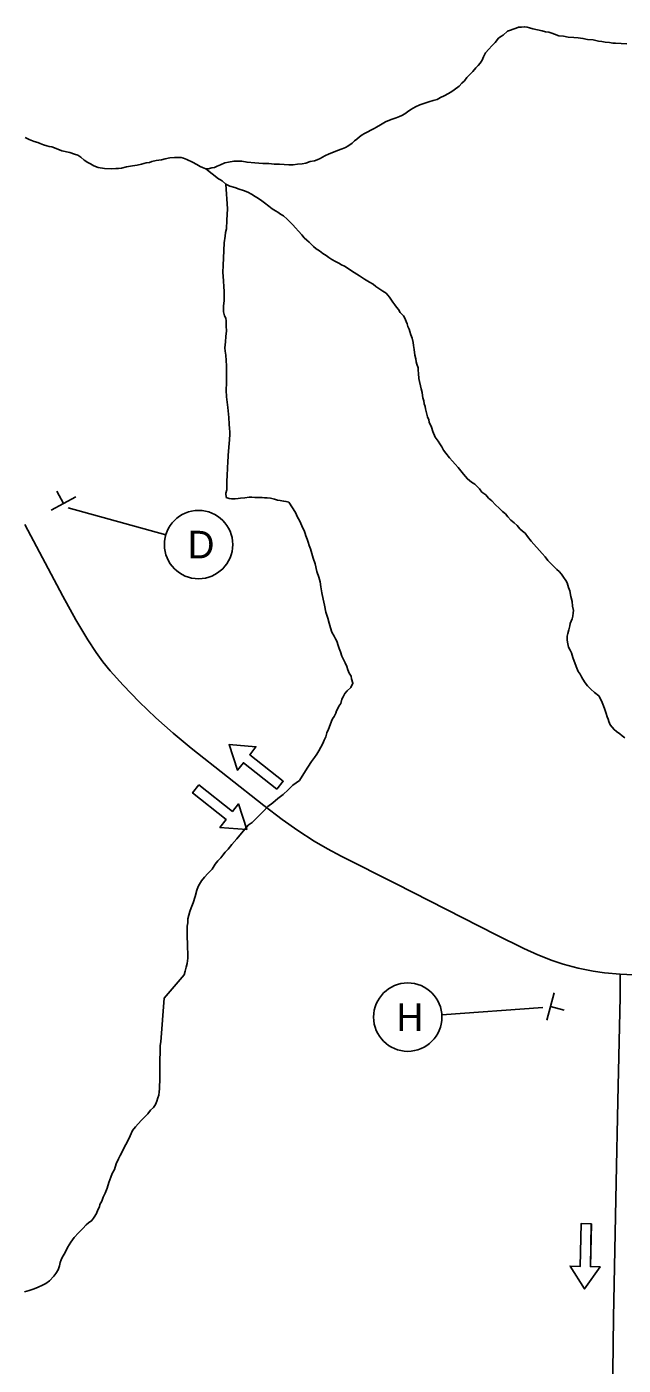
# Model space of a CAD drawing. Extents: x 1633.3 to 1707.6, y 1081.5 to 1106.
# Drawn here: x 1640.87 to 1644.25, y 1094.16 to 1101.73 of the extents above; entities that cross this region are included whole.
import ezdxf

# ---------------------------------------------------------------- set-up
doc = ezdxf.new("R2010")
doc.units = 0
for name, color, linetype in [('GM_X_County_Road', 7, 'Continuous'), ('GM_X_Minor_River', 7, 'Continuous'), ('GM_X_State_Route', 7, 'Continuous'), ('SH_Text', 7, 'Continuous'), ('SN_P_Signs', 7, 'Continuous')]:
    doc.layers.add(name, color=color, linetype=linetype)

msp = doc.modelspace()

# ---------------------------------------------------------------- linework, layer by layer
at = {"layer": 'GM_X_County_Road'}
msp.add_lwpolyline([(1644.102, 1092.8585), (1644.1321, 1092.8991), (1644.152, 1092.9386), (1644.1601, 1092.9592), (1644.1702, 1093.0024), (1644.1728, 1093.0244), (1644.1756, 1093.0686), (1644.1758, 1093.3536), (1644.1865, 1093.8566), (1644.1891, 1094.1191), (1644.194, 1094.4253), (1644.2086, 1095.1908), (1644.2171, 1095.6502), (1644.2319, 1096.2407), (1644.2313, 1096.3288), (1644.2311, 1096.3693)], dxfattribs=at)
at = {"layer": 'GM_X_Minor_River'}
for points in [[(1641.8974, 1100.9286), (1641.9189, 1100.9337), (1641.9324, 1100.9362), (1641.9486, 1100.944), (1641.9675, 1100.9518), (1641.9918, 1100.9622), (1642.0133, 1100.9673), (1642.043, 1100.9723), (1642.0698, 1100.9719), (1642.0886, 1100.9717), (1642.1181, 1100.9659), (1642.161, 1100.9627), (1642.2066, 1100.9594), (1642.2415, 1100.9589), (1642.271, 1100.9559), (1642.3006, 1100.9555), (1642.3274, 1100.9525), (1642.3542, 1100.9521), (1642.3784, 1100.9518), (1642.4026, 1100.9541), (1642.4295, 1100.9565), (1642.451, 1100.9615), (1642.4753, 1100.9693), (1642.4995, 1100.9743), (1642.5157, 1100.9794), (1642.5319, 1100.9873), (1642.559, 1101.003), (1642.5833, 1101.0134), (1642.6076, 1101.0238), (1642.6292, 1101.0315), (1642.6561, 1101.0419), (1642.675, 1101.0497), (1642.6886, 1101.0575), (1642.7129, 1101.0733), (1642.7265, 1101.0865), (1642.7401, 1101.097), (1642.7537, 1101.1103), (1642.7699, 1101.1208), (1642.7835, 1101.1286), (1642.8375, 1101.1574), (1642.851, 1101.1652), (1642.8727, 1101.1783), (1642.9024, 1101.194), (1642.9348, 1101.207), (1642.9618, 1101.2174), (1642.9807, 1101.2251), (1642.9942, 1101.2303), (1643.0105, 1101.2408), (1643.0267, 1101.2513), (1643.0457, 1101.2645), (1643.0727, 1101.2802), (1643.097, 1101.2906), (1643.124, 1101.3009), (1643.1483, 1101.3087), (1643.1725, 1101.3164), (1643.1941, 1101.3215), (1643.213, 1101.3319), (1643.2346, 1101.3424), (1643.259, 1101.3554), (1643.2779, 1101.3659), (1643.2915, 1101.3764), (1643.3186, 1101.3975), (1643.3349, 1101.4134), (1643.3485, 1101.4266), (1643.3621, 1101.4451), (1643.3812, 1101.4637), (1643.3975, 1101.4795), (1643.4139, 1101.5007), (1643.4275, 1101.5139), (1643.4384, 1101.5272), (1643.4493, 1101.5431), (1643.4576, 1101.5618), (1643.4687, 1101.5857), (1643.4877, 1101.6069), (1643.5041, 1101.6255), (1643.5231, 1101.6439), (1643.5422, 1101.6678), (1643.5558, 1101.6783), (1643.5693, 1101.6862), (1643.5937, 1101.7073), (1643.6423, 1101.7254), (1643.6558, 1101.7306), (1643.6719, 1101.7304), (1643.688, 1101.7329), (1643.7041, 1101.73), (1643.7175, 1101.7271), (1643.7362, 1101.7215), (1643.763, 1101.7158), (1643.7898, 1101.7101), (1643.8085, 1101.7045), (1643.8273, 1101.7016), (1643.8433, 1101.696), (1643.8594, 1101.6904), (1643.8834, 1101.6821), (1643.9103, 1101.6791), (1643.937, 1101.6733), (1643.9693, 1101.6729), (1643.9934, 1101.6699), (1644.0202, 1101.6669), (1644.047, 1101.6612), (1644.0792, 1101.6581)], [(1644.0792, 1101.6581), (1644.1087, 1101.6523), (1644.1274, 1101.6494), (1644.1462, 1101.6465), (1644.1703, 1101.6435), (1644.1891, 1101.6406), (1644.2052, 1101.6404), (1644.2374, 1101.6373), (1644.2696, 1101.6368)], [(1640.8603, 1101.1056), (1640.8843, 1101.0946), (1640.911, 1101.0835), (1640.9325, 1101.0779), (1640.9458, 1101.0723), (1640.9645, 1101.0641), (1640.9832, 1101.0585), (1640.9966, 1101.0556), (1641.0127, 1101.0527), (1641.0368, 1101.0444), (1641.0688, 1101.0306), (1641.1144, 1101.0219), (1641.1411, 1101.0109), (1641.1598, 1101.0053), (1641.1758, 1100.9943), (1641.1944, 1100.978), (1641.2157, 1100.9643), (1641.2317, 1100.9561), (1641.2504, 1100.9451), (1641.2744, 1100.9368), (1641.3093, 1100.931), (1641.3495, 1100.9278), (1641.3737, 1100.9301), (1641.3898, 1100.9299), (1641.406, 1100.9324), (1641.4356, 1100.94), (1641.4679, 1100.945), (1641.4948, 1100.95), (1641.519, 1100.955), (1641.546, 1100.9627), (1641.5648, 1100.9651), (1641.5783, 1100.9703), (1641.6026, 1100.9753), (1641.6322, 1100.9803), (1641.6537, 1100.9854), (1641.6806, 1100.9904), (1641.7075, 1100.9927), (1641.7263, 1100.9925), (1641.7451, 1100.9922), (1641.7585, 1100.9894), (1641.7772, 1100.9811), (1641.8092, 1100.9673), (1641.8332, 1100.9536), (1641.8519, 1100.9426), (1641.8653, 1100.9371), (1641.884, 1100.9288), (1641.8974, 1100.9286)], [(1641.884, 1100.9288), (1641.9557, 1100.8716), (1641.9638, 1100.8688), (1641.9771, 1100.8606), (1641.9983, 1100.8416), (1642.0197, 1100.8306), (1642.0491, 1100.8222), (1642.0732, 1100.8138), (1642.0972, 1100.8055), (1642.1213, 1100.7971), (1642.1427, 1100.7861), (1642.164, 1100.7724), (1642.1826, 1100.7615), (1642.2013, 1100.7479), (1642.2172, 1100.7369), (1642.2412, 1100.7179), (1642.2598, 1100.7015), (1642.2784, 1100.6906), (1642.2917, 1100.6824), (1642.3077, 1100.6715), (1642.3237, 1100.6632), (1642.345, 1100.6442), (1642.3635, 1100.6252), (1642.3768, 1100.6116), (1642.3927, 1100.5953), (1642.4086, 1100.5764), (1642.4271, 1100.5547), (1642.4403, 1100.5385), (1642.4563, 1100.5249), (1642.4696, 1100.514), (1642.4934, 1100.4895), (1642.5094, 1100.4759), (1642.528, 1100.465), (1642.5466, 1100.4487), (1642.5653, 1100.4377), (1642.5813, 1100.4268), (1642.5972, 1100.4159), (1642.6186, 1100.4049), (1642.6372, 1100.3939), (1642.6532, 1100.3857), (1642.6693, 1100.3774), (1642.7252, 1100.3419), (1642.7545, 1100.3227), (1642.7838, 1100.3036), (1642.8104, 1100.2872), (1642.8318, 1100.2762), (1642.8477, 1100.2626), (1642.8637, 1100.2516), (1642.8877, 1100.2353), (1642.9063, 1100.2243), (1642.9249, 1100.2026), (1642.9433, 1100.1729), (1642.9539, 1100.1594), (1642.9644, 1100.1459), (1642.975, 1100.1323), (1642.9855, 1100.1161), (1643.0041, 1100.0971), (1643.012, 1100.0836), (1643.0198, 1100.0648), (1643.025, 1100.0513), (1643.0275, 1100.0352), (1643.0354, 1100.0217), (1643.0406, 1100.0083), (1643.0457, 1099.9894), (1643.0535, 1099.9706), (1643.0586, 1099.9464), (1643.061, 1099.9276), (1643.0635, 1099.9062), (1643.0684, 1099.8739), (1643.0735, 1099.8524), (1643.076, 1099.8363), (1643.0785, 1099.8229), (1643.0863, 1099.8014), (1643.0862, 1099.788), (1643.0886, 1099.7692), (1643.0909, 1099.7424), (1643.1036, 1099.6833), (1643.1087, 1099.6618), (1643.1112, 1099.6457), (1643.1137, 1099.6323), (1643.1189, 1099.6161), (1643.1214, 1099.5973), (1643.1265, 1099.5839), (1643.1291, 1099.5705), (1643.1315, 1099.5543), (1643.1392, 1099.5248), (1643.1471, 1099.5086), (1643.1496, 1099.4952), (1643.1626, 1099.4655), (1643.1704, 1099.4413), (1643.1834, 1099.409), (1643.1993, 1099.3874), (1643.2098, 1099.3712), (1643.2203, 1099.355), (1643.2308, 1099.3361), (1643.2441, 1099.3198), (1643.2652, 1099.2928), (1643.2811, 1099.2738), (1643.297, 1099.2575), (1643.3129, 1099.2386), (1643.3287, 1099.2196)], [(1641.9983, 1100.8416), (1642.0073, 1100.7022), (1642.0038, 1100.6379), (1642.0005, 1100.5897), (1641.9949, 1100.5684), (1641.9946, 1100.547), (1641.9888, 1100.5095), (1641.9856, 1100.4667), (1641.9818, 1100.3811), (1641.9813, 1100.3436), (1641.9834, 1100.2953), (1641.9856, 1100.2605), (1641.988, 1100.2363), (1641.9877, 1100.2122), (1641.9874, 1100.1828), (1641.9843, 1100.1507), (1641.984, 1100.1319), (1641.9839, 1100.1185), (1641.989, 1100.097), (1641.9968, 1100.0835), (1641.9993, 1100.0674), (1641.9991, 1100.0514), (1641.999, 1100.038), (1642.0013, 1100.0112), (1641.9982, 1099.979), (1641.9952, 1099.9496), (1641.992, 1099.9148), (1641.9945, 1099.8961), (1641.9969, 1099.8746), (1642.0015, 1099.8129), (1642.0003, 1099.7165), (1641.9998, 1099.6763), (1642.002, 1099.6388), (1642.0093, 1099.5771), (1642.0139, 1099.5208), (1642.0161, 1099.4833), (1642.0185, 1099.4591), (1642.021, 1099.4403), (1642.0208, 1099.4269), (1642.0177, 1099.3948), (1642.0145, 1099.352), (1642.0112, 1099.3065), (1642.008, 1099.2664), (1642.0077, 1099.2396), (1642.0075, 1099.2209), (1642.0046, 1099.2048), (1642.0044, 1099.1914), (1642.004, 1099.162), (1642.0034, 1099.1111), (1641.9978, 1099.0924), (1642.0002, 1099.0683), (1642.0162, 1099.0627), (1642.0296, 1099.0598), (1642.0511, 1099.0596), (1642.0672, 1099.062), (1642.0807, 1099.0645), (1642.1049, 1099.0669), (1642.1291, 1099.0693), (1642.1452, 1099.0691), (1642.1613, 1099.0688), (1642.1747, 1099.0687), (1642.2016, 1099.0683), (1642.2177, 1099.0654), (1642.2311, 1099.0653), (1642.2499, 1099.065), (1642.274, 1099.0593), (1642.29, 1099.0538), (1642.3061, 1099.0509), (1642.3249, 1099.0479), (1642.3383, 1099.0451), (1642.3543, 1099.0422), (1642.3912, 1098.9828), (1642.4043, 1098.9558), (1642.4148, 1098.9369), (1642.4226, 1098.9208), (1642.433, 1098.8938), (1642.4409, 1098.8803), (1642.4461, 1098.8642), (1642.4513, 1098.8507), (1642.4591, 1098.8319), (1642.4643, 1098.8157), (1642.4694, 1098.7969), (1642.4772, 1098.7781), (1642.485, 1098.7512), (1642.4927, 1098.7243), (1642.503, 1098.692), (1642.5132, 1098.649), (1642.5235, 1098.6168), (1642.5313, 1098.5899), (1642.5363, 1098.563), (1642.5412, 1098.5281), (1642.5488, 1098.4932), (1642.5564, 1098.4583), (1642.564, 1098.418), (1642.5744, 1098.3857), (1642.582, 1098.3562), (1642.5897, 1098.3293), (1642.5975, 1098.3051), (1642.6106, 1098.2835), (1642.6185, 1098.2673), (1642.6264, 1098.2538)], [(1643.3287, 1099.2196), (1643.3446, 1099.2007), (1643.3658, 1099.1736), (1643.3897, 1099.1545), (1643.4084, 1099.1436), (1643.4216, 1099.13), (1643.4349, 1099.1164), (1643.4481, 1099.0975), (1643.4694, 1099.0838), (1643.4852, 1099.0649), (1643.5038, 1099.0486), (1643.525, 1099.0269), (1643.5463, 1099.0078), (1643.5648, 1098.9888), (1643.5808, 1098.9752), (1643.594, 1098.959), (1643.6126, 1098.94), (1643.6312, 1098.9237), (1643.6471, 1098.9101), (1643.663, 1098.8911), (1643.6789, 1098.8775), (1643.6922, 1098.8666), (1643.7054, 1098.8477), (1643.7265, 1098.8206), (1643.7901, 1098.7502), (1643.806, 1098.7312), (1643.8219, 1098.7122), (1643.8431, 1098.6905), (1643.859, 1098.6743), (1643.8722, 1098.6607), (1643.8855, 1098.6498), (1643.8988, 1098.6335), (1643.9093, 1098.6173), (1643.9225, 1098.5984), (1643.9304, 1098.5849), (1643.9356, 1098.5715), (1643.9381, 1098.558), (1643.9459, 1098.5392), (1643.9509, 1098.507), (1643.9586, 1098.4801), (1643.9609, 1098.4533), (1643.966, 1098.4291), (1643.9658, 1098.4157), (1643.9629, 1098.397), (1643.96, 1098.3809), (1643.9545, 1098.3676), (1643.9489, 1098.3543), (1643.9461, 1098.3409), (1643.9404, 1098.3196), (1643.9348, 1098.2982), (1643.9319, 1098.2822), (1643.9316, 1098.2608), (1643.9341, 1098.2393), (1643.9392, 1098.2205), (1643.9471, 1098.2043), (1643.9549, 1098.1882), (1643.9626, 1098.1613), (1643.9756, 1098.1263), (1643.9861, 1098.102), (1643.9939, 1098.0832), (1644.0044, 1098.067), (1644.0123, 1098.0535), (1644.0202, 1098.04), (1644.0333, 1098.0184), (1644.0466, 1098.0021), (1644.0651, 1097.9831), (1644.0864, 1097.9641), (1644.1103, 1097.945), (1644.1234, 1097.9207), (1644.1286, 1097.9073), (1644.1364, 1097.8884), (1644.1442, 1097.8669), (1644.152, 1097.8454), (1644.1571, 1097.8266), (1644.1624, 1097.8131), (1644.1676, 1097.7996), (1644.1754, 1097.7808), (1644.1965, 1097.7537), (1644.2098, 1097.7428), (1644.2284, 1097.7292), (1644.2417, 1097.7183), (1644.2577, 1097.7074)], [(1642.6264, 1098.2538), (1642.6341, 1098.2296), (1642.6393, 1098.2134), (1642.6471, 1098.1946), (1642.6549, 1098.1704), (1642.6627, 1098.1542), (1642.6732, 1098.1326), (1642.6837, 1098.1111), (1642.6888, 1098.0923), (1642.6966, 1098.0734), (1642.7072, 1098.0572), (1642.7096, 1098.0411), (1642.7174, 1098.0169), (1642.7064, 1097.9929), (1642.6846, 1097.9744), (1642.671, 1097.9585), (1642.6627, 1097.9399), (1642.6545, 1097.9266), (1642.6488, 1097.9026), (1642.6379, 1097.8867), (1642.6323, 1097.8733), (1642.6241, 1097.8601), (1642.6213, 1097.8467), (1642.6103, 1097.8281), (1642.6021, 1097.8148), (1642.5965, 1097.8015), (1642.5882, 1097.7802), (1642.5798, 1097.7562), (1642.5688, 1097.7349), (1642.5632, 1097.7135), (1642.5549, 1097.6949), (1642.5466, 1097.6762), (1642.5356, 1097.655), (1642.5246, 1097.6337), (1642.5136, 1097.6151), (1642.4999, 1097.5965), (1642.4835, 1097.5726), (1642.4616, 1097.5407), (1642.4397, 1097.5062), (1642.4151, 1097.4663), (1642.3771, 1097.4401), (1642.3499, 1097.4136), (1642.3228, 1097.3872), (1642.2929, 1097.3635), (1642.2631, 1097.3398), (1642.236, 1097.3187), (1642.2114, 1097.2922), (1642.1924, 1097.2737), (1642.1761, 1097.2579), (1642.1598, 1097.242), (1642.1462, 1097.2288), (1642.1245, 1097.213), (1642.0591, 1097.1362), (1642.0318, 1097.1044), (1642.01, 1097.0779), (1641.9937, 1097.0594), (1641.98, 1097.0435), (1641.9691, 1097.0275), (1641.9528, 1097.0117), (1641.9364, 1096.9931), (1641.92, 1096.9639), (1641.8955, 1096.9401), (1641.8764, 1096.9189), (1641.86, 1096.8977), (1641.8491, 1096.8791), (1641.8408, 1096.8658), (1641.8325, 1096.8445), (1641.824, 1096.8098), (1641.8128, 1096.7724), (1641.8017, 1096.7458), (1641.7934, 1096.7245), (1641.7878, 1096.7031), (1641.7821, 1096.6818), (1641.7819, 1096.6603), (1641.7789, 1096.6416), (1641.7787, 1096.6202), (1641.7784, 1096.5961), (1641.7781, 1096.572), (1641.7805, 1096.5505), (1641.7801, 1096.5211), (1641.7824, 1096.4862), (1641.782, 1096.4594), (1641.779, 1096.43), (1641.7733, 1096.4086), (1641.7677, 1096.3873), (1641.762, 1096.3659), (1641.6489, 1096.2331)], [(1641.6489, 1096.2331), (1641.6285, 1095.987), (1641.6258, 1095.9656), (1641.6258, 1095.9442), (1641.6257, 1095.9228), (1641.623, 1095.8907), (1641.6229, 1095.8666), (1641.6228, 1095.8345), (1641.6228, 1095.8078), (1641.6227, 1095.7837), (1641.6227, 1095.7623), (1641.6226, 1095.7409), (1641.6226, 1095.7195), (1641.6199, 1095.7034), (1641.6171, 1095.6847), (1641.6118, 1095.6687), (1641.6064, 1095.65), (1641.5983, 1095.6313), (1641.5876, 1095.6152), (1641.5715, 1095.5992), (1641.5554, 1095.5779), (1641.5393, 1095.5619), (1641.5205, 1095.5432), (1641.5017, 1095.5219), (1641.4856, 1095.5059), (1641.4695, 1095.4845), (1641.4561, 1095.4551), (1641.4426, 1095.4257), (1641.4319, 1095.4044), (1641.3996, 1095.3429), (1641.3889, 1095.3243), (1641.3754, 1095.2949), (1641.3673, 1095.2628), (1641.3539, 1095.2414), (1641.3458, 1095.22), (1641.335, 1095.1906), (1641.3243, 1095.1586), (1641.3135, 1095.1292), (1641.3027, 1095.1078), (1641.2947, 1095.0837), (1641.2839, 1095.0651), (1641.2812, 1095.0517), (1641.2732, 1095.0357), (1641.2651, 1095.0143), (1641.2516, 1094.9929), (1641.2382, 1094.9742), (1641.2195, 1094.9609), (1641.2061, 1094.9503), (1641.1873, 1094.9289), (1641.1631, 1094.9049), (1641.139, 1094.8782), (1641.1202, 1094.8515), (1641.1014, 1094.8222), (1641.0853, 1094.7901), (1641.0718, 1094.7688), (1641.0638, 1094.7527), (1641.0584, 1094.7367), (1641.0557, 1094.718), (1641.0476, 1094.6966), (1641.0342, 1094.6752), (1641.0234, 1094.6592), (1640.9993, 1094.6325), (1640.9779, 1094.6192), (1640.9591, 1094.6086), (1640.935, 1094.598), (1640.9109, 1094.5873), (1640.8841, 1094.5794), (1640.8573, 1094.5715)]]:
    msp.add_lwpolyline(points, dxfattribs=at)
at = {"layer": 'GM_X_State_Route'}
msp.add_lwpolyline([(1640.8583, 1098.9156), (1641.0733, 1098.5093), (1641.1474, 1098.3754), (1641.2152, 1098.2631), (1641.2633, 1098.1904), (1641.3016, 1098.1375), (1641.3428, 1098.0868), (1641.4153, 1098.0053), (1641.5065, 1097.9111), (1641.601, 1097.8203), (1641.6992, 1097.7334), (1641.8003, 1097.6498), (1642.2127, 1097.3245), (1642.3174, 1097.2455), (1642.4062, 1097.182), (1642.4978, 1097.1227), (1642.5729, 1097.0783), (1642.6499, 1097.0371), (1642.9631, 1096.8809), (1643.5285, 1096.5921), (1643.6856, 1096.515), (1643.7652, 1096.4792), (1643.8463, 1096.4472), (1643.9083, 1096.4268), (1643.9925, 1096.4041), (1644.0779, 1096.3872), (1644.1425, 1096.3774), (1644.2311, 1096.3693), (1644.4915, 1096.3571)], dxfattribs=at)
at = {"layer": 'SH_Text'}
for p, q in [((1641.1051, 1099.0095), (1641.6569, 1098.8557)), ((1642.0155, 1097.6695), (1642.1681, 1097.6568)), ((1642.0155, 1097.6695), (1642.0628, 1097.5238)), ((1642.1681, 1097.6568), (1642.1327, 1097.6121)), ((1642.0628, 1097.5238), (1642.0967, 1097.5666)), ((1642.0967, 1097.5666), (1642.2864, 1097.4163)), ((1642.1327, 1097.6121), (1642.3224, 1097.4618)), ((1641.8093, 1097.3954), (1641.8453, 1097.4408)), ((1642.035, 1097.2905), (1641.8453, 1097.4408)), ((1642.3224, 1097.4618), (1642.2864, 1097.4163)), ((1641.9989, 1097.245), (1641.8093, 1097.3954)), ((1642.0689, 1097.3333), (1642.035, 1097.2905)), ((1642.1161, 1097.1876), (1642.0689, 1097.3333)), ((1641.9636, 1097.2004), (1641.9989, 1097.245)), ((1642.1161, 1097.1876), (1641.9636, 1097.2004)), ((1643.7925, 1096.1813), (1643.2212, 1096.1385)), ((1644.0047, 1094.7153), (1644.0099, 1094.9572)), ((1644.0099, 1094.9572), (1644.0678, 1094.956)), ((1644.0628, 1094.714), (1644.0678, 1094.956)), ((1644.0299, 1094.5872), (1643.9478, 1094.7165)), ((1643.9478, 1094.7165), (1644.0047, 1094.7153)), ((1644.0299, 1094.5872), (1644.1173, 1094.7129)), ((1644.1173, 1094.7129), (1644.0628, 1094.714))]:
    msp.add_line(p, q, dxfattribs=at)
for points in [[(1640.8583, 1098.9156), (1641.0733, 1098.5093), (1641.1474, 1098.3754), (1641.2152, 1098.2631), (1641.2633, 1098.1904), (1641.3016, 1098.1375), (1641.3428, 1098.0868), (1641.4153, 1098.0053), (1641.5065, 1097.9111), (1641.601, 1097.8203), (1641.6992, 1097.7334), (1641.8003, 1097.6498), (1642.2127, 1097.3245), (1642.3174, 1097.2455), (1642.4062, 1097.182), (1642.4978, 1097.1227), (1642.5729, 1097.0783), (1642.6499, 1097.0371), (1642.9631, 1096.8809), (1643.5285, 1096.5921), (1643.6856, 1096.515), (1643.7652, 1096.4792), (1643.8463, 1096.4472), (1643.9083, 1096.4268), (1643.9925, 1096.4041), (1644.0779, 1096.3872), (1644.1425, 1096.3774), (1644.2311, 1096.3693)], [(1644.102, 1092.8585), (1644.1321, 1092.8991), (1644.152, 1092.9386), (1644.1601, 1092.9592), (1644.1702, 1093.0024), (1644.1728, 1093.0244), (1644.1756, 1093.0686), (1644.1758, 1093.3536), (1644.1865, 1093.8566), (1644.1891, 1094.1191), (1644.194, 1094.4253), (1644.2086, 1095.1908), (1644.2171, 1095.6502), (1644.2319, 1096.2407), (1644.2313, 1096.3288), (1644.2311, 1096.3693)]]:
    msp.add_lwpolyline(points, dxfattribs=at)
for points in [[(1642.2864, 1097.4163), (1642.0967, 1097.5666), (1642.0628, 1097.5238), (1642.0155, 1097.6695), (1642.1681, 1097.6568), (1642.1327, 1097.6121), (1642.3224, 1097.4618)], [(1641.8453, 1097.4408), (1642.035, 1097.2905), (1642.0689, 1097.3333), (1642.1162, 1097.1876), (1641.9636, 1097.2004), (1641.999, 1097.245), (1641.8093, 1097.3954)], [(1644.0679, 1094.956), (1644.0628, 1094.714), (1644.1173, 1094.7129), (1644.0299, 1094.5872), (1643.9478, 1094.7165), (1644.0048, 1094.7153), (1644.0099, 1094.9572)]]:
    msp.add_lwpolyline(points, close=True, dxfattribs=at)
for centre in [(1641.8428, 1098.8016), (1643.028, 1096.1262)]:
    msp.add_circle(centre, 0.1936, dxfattribs=at)
at = {"layer": 'SN_P_Signs'}
for p, q in [((1641.0784, 1099.0341), (1641.04, 1099.1043)), ((1641.0083, 1098.9957), (1641.1486, 1099.0725)), ((1643.8575, 1096.2645), (1643.8157, 1096.11)), ((1643.8366, 1096.1872), (1643.9138, 1096.1664))]:
    msp.add_line(p, q, dxfattribs=at)

# ---------------------------------------------------------------- texts
at = {"layer": 'SH_Text'}
for s, p in [('D', (1641.782, 1098.7236)), ('H', (1642.9648, 1096.0482))]:
    msp.add_text(s, height=0.156, dxfattribs=at).set_placement(p)

doc.saveas('drawing.dxf')
